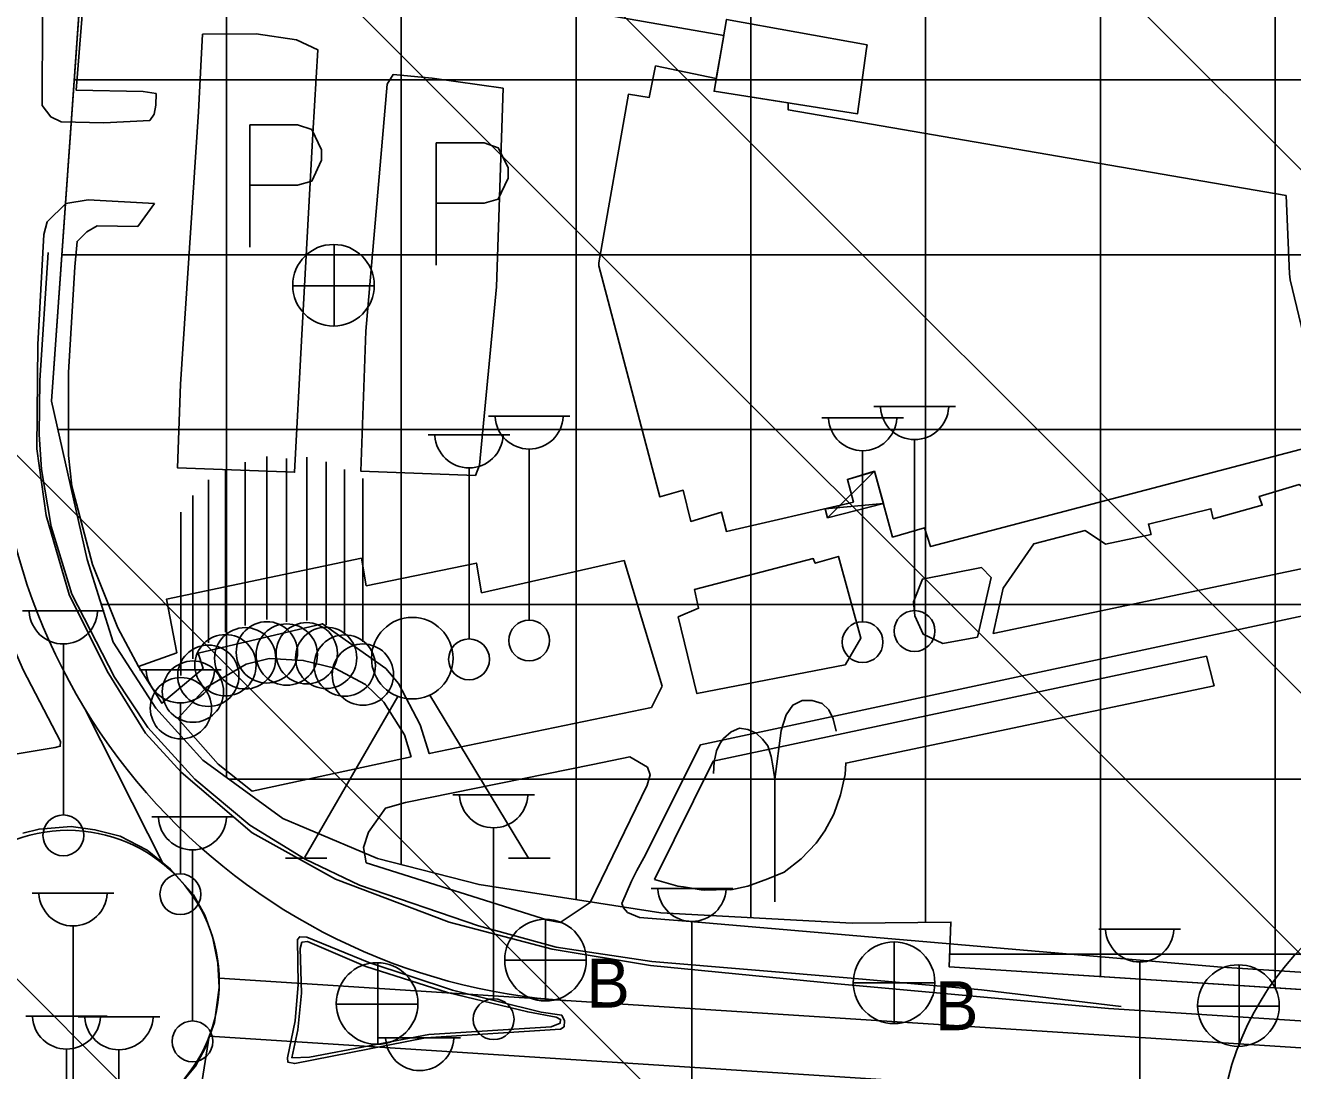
# Model space of a CAD drawing. Extents: x 417995 to 421451, y 4454518 to 4458015.
# Drawn here: x 420383.4 to 420492.2, y 4456336 to 4456425.7 of the extents above; entities that cross this region are included whole.
import ezdxf

# ---------------------------------------------------------------- set-up
doc = ezdxf.new("R2010")
doc.units = 0
for name, color, linetype in [('ADAKENARI', 7, 'Continuous'), ('B_Imalat', 7, 'Continuous'), ('B_Sundurma', 7, 'Continuous'), ('B_Teras', 7, 'Continuous'), ('Hid_Havuz', 7, 'Continuous'), ('KALDIRIM_FAT', 7, 'Continuous'), ('KD_DAIRE', 7, 'Continuous'), ('O_Park_Bahce', 7, 'Continuous'), ('PL_TİCARET', 7, 'Continuous'), ('S_Bayrak_Diregi', 7, 'Continuous'), ('S_Cad_Sok_Lambasi', 7, 'Continuous'), ('S_Heykel', 7, 'Continuous'), ('S_Otopark', 7, 'Continuous'), ('S_Rogar_Kapagi', 7, 'Continuous'), ('S_Rogar_Kapagi_Buski', 7, 'Continuous'), ('Sinir_Duvar_tek_tarafa_ait', 7, 'Continuous'), ('Sinir_Ist_Duvari', 7, 'Continuous'), ('Sinir_Parmaklik_bir_taraf', 7, 'Continuous'), ('SN_TR_SIVILASMA', 7, 'Continuous'), ('TRFAT_TİCARET', 7, 'Continuous'), ('Yol_Kaldirim_kenari_bordurtasi', 7, 'Continuous'), ('Yol_Sose', 7, 'Continuous')]:
    doc.layers.add(name, color=color, linetype=linetype)

msp = doc.modelspace()

# ---------------------------------------------------------------- linework, layer by layer
at = {"layer": 'ADAKENARI'}
for p, q in [((420385.69, 4456393.42), (420394.63, 4456520.03)), ((420388.74, 4456379.85), (420385.69, 4456393.42)), ((420390.97, 4456372.75), (420388.74, 4456379.85)), ((420394.62, 4456367.08), (420390.97, 4456372.75)), ((420398.67, 4456362.62), (420394.62, 4456367.08)), ((420405.54, 4456357.63), (420398.67, 4456362.62)), ((420413.66, 4456354.19), (420405.54, 4456357.63)), ((420422.37, 4456351.96), (420413.66, 4456354.19)), ((420437.97, 4456349.54), (420422.37, 4456351.96)), ((420454.39, 4456348.66), (420437.97, 4456349.54)), ((420462.86, 4456348.74), (420454.39, 4456348.66)), ((420462.71, 4456344.9), (420462.86, 4456348.74)), ((420621.4, 4456334.69), (420462.71, 4456344.9))]:
    msp.add_line(p, q, dxfattribs=at)
at = {"layer": 'B_Imalat'}
msp.add_lwpolyline([(420432.7, 4456426.66), (420443.36, 4456424.79), (420442.72, 4456421.12), (420437.51, 4456422.19), (420436.96, 4456419.47), (420435.19, 4456419.76), (420432.66, 4456405.28), (420432.66, 4456405.04), (420437.89, 4456385.21), (420439.89, 4456385.79), (420440.53, 4456383.11), (420443.16, 4456383.91), (420443.6, 4456382.25), (420443.6, 4456382.25), (420454.49, 4456384.75), (420453.98, 4456386.71), (420453.98, 4456386.71), (420456.21, 4456387.38), (420456.29, 4456387.41), (420457.85, 4456381.77), (420457.85, 4456381.77), (420460.6, 4456382.57), (420461.11, 4456380.95), (420494.57, 4456389.74)], dxfattribs=at)
at = {"layer": 'B_Sundurma'}
for p, q in [((420452.27, 4456383.42), (420456.29, 4456387.41)), ((420452.08, 4456384.2), (420457.06, 4456384.64))]:
    msp.add_line(p, q, dxfattribs=at)
msp.add_lwpolyline([(420452.08, 4456384.2), (420452.27, 4456383.42), (420457.06, 4456384.64), (420456.29, 4456387.41), (420453.98, 4456386.71), (420453.98, 4456386.71), (420454.49, 4456384.75)], close=True, dxfattribs=at)
at = {"layer": 'B_Teras'}
msp.add_lwpolyline([(420493.28, 4456398.38), (420491.96, 4456403.84), (420491.92, 4456404.34), (420491.62, 4456411.06), (420448.88, 4456418.42), (420448.9, 4456419.01), (420442.53, 4456420.01), (420443.36, 4456424.79), (420432.7, 4456426.66)], dxfattribs=at)
msp.add_lwpolyline([(420455.67, 4456423.98), (420455.62, 4456423.68), (420454.85, 4456418.08), (420442.53, 4456420.01), (420442.53, 4456420.01), (420443.61, 4456426.18)], close=True, dxfattribs=at)
at = {"layer": 'Hid_Havuz'}
msp.add_lwpolyline([(420437.43, 4456352.41), (420439.44, 4456351.83), (420439.91, 4456351.77), (420441.43, 4456351.5), (420441.74, 4456351.49), (420443.71, 4456351.53), (420443.98, 4456351.52), (420445.42, 4456351.83), (420447.15, 4456352.44), (420448.54, 4456353.03), (420450.02, 4456354.17), (420451.31, 4456355.51), (420452.03, 4456356.57), (420452.82, 4456358), (420453.38, 4456359.65), (420453.78, 4456361.4), (420453.84, 4456362.38), (420485.44, 4456369.02), (420485.38, 4456369.2), (420484.78, 4456371.55), (420442.46, 4456362.55)], close=True, dxfattribs=at)
for points in [[(420453, 4456365.12), (420452.76, 4456366.17), (420452.37, 4456366.94), (420451.81, 4456367.5), (420450.94, 4456367.75), (420450.1, 4456367.75), (420449.29, 4456367.36), (420448.73, 4456366.52), (420448.28, 4456365.19), (420447.75, 4456360.99)], [(420442.5, 4456361.48), (420442.54, 4456362.5), (420442.75, 4456363.44), (420443.03, 4456364.04), (420443.34, 4456364.49), (420444.01, 4456365.05), (420444.71, 4456365.37), (420445.44, 4456365.26), (420446.14, 4456364.95), (420446.7, 4456364.42), (420447.16, 4456363.86), (420447.44, 4456362.95), (420447.58, 4456362.15), (420447.75, 4456360.99), (420447.75, 4456350.49)]]:
    msp.add_lwpolyline(points, dxfattribs=at)
at = {"layer": 'KALDIRIM_FAT'}
for p, q in [((420395.3, 4456353.69), (420388.57, 4456366.98)), ((420619.92, 4456329.77), (420400.07, 4456343.92)), ((420399.21, 4456338.96), (420396.64, 4456322.5)), ((420619.6, 4456324.78), (420399.21, 4456338.96))]:
    msp.add_line(p, q, dxfattribs=at)
msp.add_circle((420387.08, 4456343.62), 13, dxfattribs=at)
msp.add_arc((420433.33, 4456394.34), 52.45, 175.9611, 266.3195, dxfattribs=at)
at = {"layer": 'KD_DAIRE'}
msp.add_circle((420510.85, 4456329.09), 25, dxfattribs=at)
at = {"layer": 'O_Park_Bahce'}
for points in [[(420466.48, 4456373.5), (420500.26, 4456380.6), (420500.26, 4456380.6), (420492.75, 4456386.27), (420489.32, 4456385.25), (420489.58, 4456384.5), (420485.37, 4456383.34), (420485.17, 4456384.2), (420479.81, 4456382.88), (420480.03, 4456382), (420476.11, 4456381.16), (420474.39, 4456382.33), (420469.97, 4456381.2), (420467.33, 4456377.39), (420466.48, 4456373.5)], [(420438.08, 4456368.97), (420437.16, 4456367.15), (420418.1, 4456363.2), (420417.32, 4456365.66), (420415.47, 4456369.21), (420414.38, 4456370.49), (420408.93, 4456374.33), (420398.28, 4456371.81), (420398.7, 4456370.5), (420395.15, 4456367.51), (420393.15, 4456370.67), (420396.43, 4456371.84), (420395.54, 4456376.43), (420412.28, 4456379.96), (420412.69, 4456377.6), (420422.14, 4456379.54), (420422.59, 4456377), (420434.81, 4456379.77)], [(420439.45, 4456374.93), (420441.06, 4456368.34), (420453.79, 4456370.81), (420453.82, 4456370.84), (420455.13, 4456373.1), (420453.2, 4456380.11), (420451.22, 4456379.52), (420451.19, 4456379.6), (420451.05, 4456379.92), (420440.87, 4456377.28), (420441.21, 4456375.66), (420439.45, 4456374.93)], [(420434.81, 4456379.77), (420438.08, 4456368.97)], [(420465.14, 4456373.19), (420466.32, 4456378.29), (420465.48, 4456379.15), (420460.41, 4456378.16), (420459.64, 4456376.21), (420459.75, 4456375), (420460.49, 4456373.44), (420462.17, 4456372.65)], [(420435.9, 4456353.17), (420436.52, 4456354.25), (420441.38, 4456363.95), (420476.86, 4456371.55), (420501.9, 4456376.91)], [(420462.17, 4456372.65), (420465.14, 4456373.19)], [(420416.54, 4456362.91), (420415.98, 4456364.81), (420414.19, 4456367.61), (420412.63, 4456369.13), (420409.98, 4456370.52), (420407.28, 4456371.19), (420404.37, 4456371.35), (420402.39, 4456370.86), (420398.96, 4456368.86), (420396.52, 4456366.21), (420399.97, 4456362.3), (420402.89, 4456359.98), (420412.72, 4456362.1)], [(420435.3, 4456362.93), (420436.82, 4456362.02), (420437.05, 4456361.37), (420436.8, 4456360.48), (420431.91, 4456350.43), (420429.34, 4456348.72), (420428.27, 4456348.9), (420412.69, 4456353.84), (420412.46, 4456355.14), (420412.89, 4456356.45), (420414.34, 4456358.51), (420416.05, 4456359.01), (420432.13, 4456362.27)], [(420412.72, 4456362.1), (420416.54, 4456362.91)], [(420432.13, 4456362.27), (420435.3, 4456362.93)], [(420500.03, 4456343.98), (420486.07, 4456344.88), (420440.13, 4456348.83), (420436.15, 4456349.14), (420435.12, 4456349.57), (420434.77, 4456349.98), (420434.62, 4456350.33), (420435.46, 4456352.26), (420435.9, 4456353.17)]]:
    msp.add_lwpolyline(points, dxfattribs=at)
at = {"layer": 'PL_TİCARET'}
msp.add_lwpolyline([(420623.45, 4456037.14), (420640, 4456310.1), (420637.88, 4456323.02), (420634.68, 4456327.8), (420629.47, 4456331.61), (420628.47, 4456331.87), (420624.59, 4456333.76), (420621.4, 4456334.69), (420462.71, 4456344.9), (420462.86, 4456348.74), (420454.39, 4456348.66), (420437.97, 4456349.54), (420422.37, 4456351.96), (420413.66, 4456354.19), (420405.54, 4456357.63), (420398.67, 4456362.62), (420394.62, 4456367.08), (420390.97, 4456372.75), (420388.74, 4456379.85), (420385.69, 4456393.42), (420394.63, 4456520.03)], dxfattribs=at)
at = {"layer": 'S_Bayrak_Diregi'}
for p, q in [((420404.16, 4456374.69), (420404.16, 4456388.69)), ((420407.58, 4456374.61), (420407.58, 4456388.61)), ((420400.61, 4456373.6), (420400.61, 4456387.6)), ((420402.3, 4456374.19), (420402.3, 4456388.19)), ((420405.86, 4456374.51), (420405.86, 4456388.51)), ((420409.24, 4456374.23), (420409.24, 4456388.23)), ((420410.83, 4456373.57), (420410.83, 4456387.57)), ((420399.14, 4456372.69), (420399.14, 4456386.69)), ((420412.39, 4456372.79), (420412.39, 4456386.79)), ((420397.81, 4456371.33), (420397.81, 4456385.33)), ((420396.78, 4456369.9), (420396.78, 4456383.9))]:
    msp.add_line(p, q, dxfattribs=at)
for centre in [(420404.16, 4456371.88), (420407.58, 4456371.8), (420400.61, 4456370.78), (420402.3, 4456371.37), (420405.87, 4456371.69), (420409.25, 4456371.41), (420410.84, 4456370.75), (420399.14, 4456369.87), (420412.4, 4456369.97), (420397.82, 4456368.51), (420396.79, 4456367.09)]:
    msp.add_circle(centre, 2.63, dxfattribs=at)
at = {"layer": 'S_Cad_Sok_Lambasi'}
for p, q in [((420456.24, 4456392.96), (420463.24, 4456392.96)), ((420423.17, 4456392.15), (420430.17, 4456392.15)), ((420451.78, 4456392.01), (420458.78, 4456392.01)), ((420418.01, 4456390.53), (420425.01, 4456390.53)), ((420459.74, 4456375.46), (420459.74, 4456390.13)), ((420426.67, 4456374.65), (420426.67, 4456389.32)), ((420455.28, 4456374.51), (420455.28, 4456389.18)), ((420421.51, 4456373.03), (420421.51, 4456387.7)), ((420383.2, 4456375.43), (420390.2, 4456375.43)), ((420386.7, 4456357.93), (420386.7, 4456372.6)), ((420393.24, 4456370.38), (420400.24, 4456370.38)), ((420396.74, 4456352.88), (420396.74, 4456367.56)), ((420420.12, 4456359.66), (420427.12, 4456359.66)), ((420394.28, 4456357.76), (420401.28, 4456357.76)), ((420423.62, 4456342.16), (420423.62, 4456356.83)), ((420397.78, 4456340.26), (420397.78, 4456354.93)), ((420437.14, 4456351.62), (420444.14, 4456351.62)), ((420384.03, 4456351.23), (420391.03, 4456351.23)), ((420387.53, 4456333.73), (420387.53, 4456348.41)), ((420440.64, 4456334.12), (420440.64, 4456348.8)), ((420475.56, 4456348.15), (420482.56, 4456348.15)), ((420479.06, 4456330.65), (420479.06, 4456345.32)), ((420383.47, 4456340.68), (420390.47, 4456340.68)), ((420387.97, 4456340.62), (420394.97, 4456340.62)), ((420413.78, 4456338.82), (420420.78, 4456338.82)), ((420386.97, 4456323.18), (420386.97, 4456337.85)), ((420391.47, 4456323.12), (420391.47, 4456337.79))]:
    msp.add_line(p, q, dxfattribs=at)
for centre in [(420426.67, 4456372.9), (420455.28, 4456372.76), (420459.74, 4456373.71), (420421.51, 4456371.28), (420386.7, 4456356.18), (420396.74, 4456351.13), (420423.62, 4456340.41), (420397.78, 4456338.51)]:
    msp.add_circle(centre, 1.75, dxfattribs=at)
for centre in [(420459.74, 4456393.06), (420426.67, 4456392.25), (420455.28, 4456392.11), (420421.51, 4456390.63), (420386.7, 4456375.53), (420396.74, 4456370.48), (420423.62, 4456359.76), (420397.78, 4456357.86), (420440.64, 4456351.73), (420387.53, 4456351.34), (420479.06, 4456348.25), (420386.97, 4456340.78), (420391.47, 4456340.72), (420417.28, 4456338.93)]:
    msp.add_arc(centre, 2.93, 183.298, 356.9072, dxfattribs=at)
at = {"layer": 'S_Heykel'}
for p, q in [((420407.43, 4456354.31), (420415.41, 4456368.1)), ((420426.61, 4456354.24), (420418.14, 4456368.21)), ((420405.75, 4456354.24), (420409.32, 4456354.24)), ((420424.89, 4456354.24), (420428.46, 4456354.24))]:
    msp.add_line(p, q, dxfattribs=at)
msp.add_circle((420416.64, 4456371.38), 3.5, dxfattribs=at)
at = {"layer": 'S_Otopark'}
for points in [[(420402.69, 4456417.14), (420406.78, 4456417.14)], [(420402.69, 4456406.64), (420402.69, 4456417.14)], [(420406.78, 4456417.14), (420408.01, 4456416.72), (420408.85, 4456415), (420408.85, 4456414.09), (420408.01, 4456412.31), (420406.78, 4456411.96)], [(420418.7, 4456415.59), (420422.8, 4456415.59)], [(420418.7, 4456405.09), (420418.7, 4456415.59)], [(420422.8, 4456415.59), (420424.02, 4456415.17), (420424.86, 4456413.46), (420424.86, 4456412.55), (420424.02, 4456410.76), (420422.8, 4456410.41)], [(420406.78, 4456411.96), (420402.69, 4456411.96)], [(420422.8, 4456410.41), (420418.7, 4456410.41)]]:
    msp.add_lwpolyline(points, dxfattribs=at)
at = {"layer": 'S_Rogar_Kapagi'}
for p, q in [((420409.93, 4456399.84), (420409.93, 4456406.84)), ((420406.36, 4456403.31), (420413.36, 4456403.31)), ((420413.67, 4456338.23), (420413.67, 4456345.23)), ((420487.59, 4456338.05), (420487.59, 4456345.05)), ((420410.1, 4456341.7), (420417.1, 4456341.7)), ((420484.02, 4456341.52), (420491.02, 4456341.52))]:
    msp.add_line(p, q, dxfattribs=at)
for centre in [(420409.88, 4456403.37), (420413.62, 4456341.76), (420487.53, 4456341.58)]:
    msp.add_circle(centre, 3.5, dxfattribs=at)
at = {"layer": 'S_Rogar_Kapagi_Buski'}
for p, q in [((420428.07, 4456348.98), (420428.07, 4456341.98)), ((420457.98, 4456347.04), (420457.98, 4456340.04)), ((420424.57, 4456345.48), (420431.57, 4456345.48)), ((420454.48, 4456343.54), (420461.48, 4456343.54))]:
    msp.add_line(p, q, dxfattribs=at)
for centre in [(420428.07, 4456345.48), (420457.98, 4456343.54)]:
    msp.add_circle(centre, 3.5, dxfattribs=at)
at = {"layer": 'Sinir_Duvar_tek_tarafa_ait'}
msp.add_lwpolyline([(420389.19, 4456379.42), (420387.42, 4456386.13)], dxfattribs=at)
at = {"layer": 'Sinir_Ist_Duvari'}
for points in [[(420393.55, 4456419.99), (420387.79, 4456420.11), (420389.14, 4456436.98), (420393.71, 4456436.17), (420394.12, 4456439.78)], [(420387.42, 4456386.13), (420387.15, 4456388.77), (420387.13, 4456395.89), (420387.68, 4456404.94), (420387.88, 4456407.13), (420388.7, 4456407.96), (420389.61, 4456408.47), (420393.08, 4456408.4)]]:
    msp.add_lwpolyline(points, dxfattribs=at)
at = {"layer": 'Sinir_Parmaklik_bir_taraf'}
for points in [[(420422.33, 4456348.43), (420412.11, 4456351.9), (420407.44, 4456354.14), (420402.7, 4456357.06), (420397.97, 4456361), (420393.95, 4456365.43), (420391.08, 4456369.75), (420387.43, 4456376.88), (420385.66, 4456382.67), (420384.83, 4456387.57), (420384.61, 4456390.57), (420384.69, 4456395.2), (420385.39, 4456406.18)], [(420477.46, 4456341.51), (420465.47, 4456342.94), (420454.3, 4456343.92), (420437.19, 4456345.37), (420428.98, 4456346.6), (420422.33, 4456348.43)], [(420406.3, 4456337.1), (420406.82, 4456339.51), (420407.13, 4456342.65), (420407.01, 4456346.49), (420407.17, 4456347.02), (420407.65, 4456347.08), (420412.65, 4456344.94), (420419.65, 4456342.69), (420426.55, 4456341.04), (420428.98, 4456340.59), (420429.36, 4456340.39), (420429.32, 4456340.06), (420428.55, 4456339.76), (420418.06, 4456339.11), (420407.81, 4456337.17), (420406.3, 4456337.1)]]:
    msp.add_lwpolyline(points, dxfattribs=at)
at = {"layer": 'SN_TR_SIVILASMA'}
for p, q in [((421273.02, 4455633.15), (420276.28, 4456629.89)), ((421272.55, 4455588.71), (420264.03, 4456597.24)), ((421272.32, 4455566.5), (420257.91, 4456580.91)), ((421271.63, 4455499.84), (420239.54, 4456531.93)), ((421271.16, 4455455.4), (420227.3, 4456499.27))]:
    msp.add_line(p, q, dxfattribs=at)
at = {"layer": 'TRFAT_TİCARET'}
for p, q in [((420490.69, 4456343.1), (420490.69, 4456569.86)), ((420475.69, 4456344.06), (420475.69, 4456562.5)), ((420460.69, 4456348.72), (420460.69, 4456555.15)), ((420445.69, 4456349.12), (420445.69, 4456547.79)), ((420430.69, 4456350.67), (420430.69, 4456540.44)), ((420415.69, 4456353.67), (420415.69, 4456533.08)), ((420400.69, 4456361.15), (420400.69, 4456525.73)), ((420387.64, 4456420.99), (420736.45, 4456420.99)), ((420386.58, 4456405.99), (420735.43, 4456405.99)), ((420386.24, 4456390.99), (420734.4, 4456390.99)), ((420389.95, 4456375.99), (420733.38, 4456375.99)), ((420400.91, 4456360.99), (420732.36, 4456360.99)), ((420462.75, 4456345.99), (420731.34, 4456345.99))]:
    msp.add_line(p, q, dxfattribs=at)
at = {"layer": 'Yol_Kaldirim_kenari_bordurtasi'}
for points in [[(420394.66, 4456419.82), (420393.55, 4456419.99)], [(420394.52, 4456410.39), (420393.08, 4456408.4)], [(420389.19, 4456379.42), (420391.38, 4456373.98), (420393.15, 4456370.67)]]:
    msp.add_lwpolyline(points, dxfattribs=at)
at = {"layer": 'Yol_Sose'}
for points in [[(420388.62, 4456479.25), (420386.78, 4456453.17), (420384.9, 4456426.45), (420384.87, 4456418.8), (420385.62, 4456417.81), (420386.52, 4456417.4), (420390.18, 4456417.29), (420394.11, 4456417.51), (420394.48, 4456418.04), (420394.63, 4456418.82), (420394.66, 4456419.82)], [(420398.3, 4456418.25), (420396.76, 4456394.88), (420396.5, 4456387.7), (420406.54, 4456387.33), (420407.12, 4456398.61), (420408.1, 4456416.36), (420408.54, 4456423.56), (420406.71, 4456424.43), (420403.23, 4456424.93), (420398.65, 4456424.9), (420398.52, 4456422.75)], [(420398.3, 4456418.25), (420398.52, 4456422.75)], [(420418.35, 4456421.13), (420415.01, 4456421.46), (420414.47, 4456420.61), (420412.65, 4456399.43), (420412.23, 4456387.42), (420422.06, 4456387.06), (420422.41, 4456387.93), (420423.86, 4456403.23), (420424.44, 4456420.28)], [(420424.44, 4456420.28), (420418.35, 4456421.13)], [(420394.52, 4456410.39), (420388.84, 4456410.7), (420386.92, 4456410.39), (420385.31, 4456408.82), (420385.03, 4456407.73), (420384.51, 4456398.28), (420384.41, 4456389.34), (420385.22, 4456383.61), (420387.19, 4456376.84), (420390.47, 4456370.26), (420393.74, 4456364.95), (420396.8, 4456361.61), (420402.91, 4456356.41), (420410.06, 4456352.42), (420419.81, 4456348.75), (420428.63, 4456346.41), (420437.07, 4456345.03), (420453.14, 4456343.44), (420476.37, 4456341.33), (420499.49, 4456339.83), (420513.39, 4456338.86)], [(420379.47, 4456362.84), (420379.26, 4456363.07), (420379.2, 4456363.34), (420379.32, 4456366.39), (420379.52, 4456370.18), (420379.47, 4456372.85), (420378.84, 4456378.18), (420378.71, 4456382.16), (420378.83, 4456382.46), (420379.4, 4456382.49), (420379.59, 4456382.12), (420379.79, 4456381.08), (420381.33, 4456374.8), (420383.25, 4456370.37), (420386.45, 4456364.22), (420386.43, 4456363.83), (420385.99, 4456363.71), (420382.04, 4456363.07)], [(420383.23, 4456356.36), (420384.62, 4456356.72), (420387.37, 4456356.94), (420389.4, 4456356.66), (420391.58, 4456356.11), (420393.9, 4456354.9)], [(420393.9, 4456354.9), (420395.9, 4456353.29), (420397.86, 4456351.08), (420398.83, 4456349.34), (420399.49, 4456347.51), (420399.95, 4456345.23), (420400.06, 4456343.13)], [(420429.71, 4456340.26), (420429.67, 4456339.77), (420429.37, 4456339.56), (420417.76, 4456338.81), (420406.56, 4456336.6), (420405.96, 4456336.73), (420405.92, 4456337.1), (420406.59, 4456340.26), (420406.86, 4456343.39), (420406.78, 4456347.24), (420406.98, 4456347.48), (420407.6, 4456347.45), (420412.9, 4456345.28), (420420.09, 4456342.9), (420427.71, 4456341.03)], [(420400.06, 4456343.13), (420399.66, 4456340.14), (420398.87, 4456337.92), (420398.03, 4456336.39), (420396.58, 4456334.64), (420395.07, 4456333.29), (420393.57, 4456332.31), (420391.42, 4456331.28), (420388.68, 4456330.66), (420386.43, 4456330.53), (420384.17, 4456330.83), (420381.68, 4456331.61)], [(420427.71, 4456341.03), (420429.47, 4456340.76), (420429.71, 4456340.26)]]:
    msp.add_lwpolyline(points, dxfattribs=at)

# ---------------------------------------------------------------- texts
at = {"layer": 'S_Rogar_Kapagi_Buski'}
for p in [(420431.57, 4456341.41), (420461.48, 4456339.47)]:
    msp.add_text('B', height=4.2, dxfattribs=at).set_placement(p)

doc.saveas('drawing.dxf')
